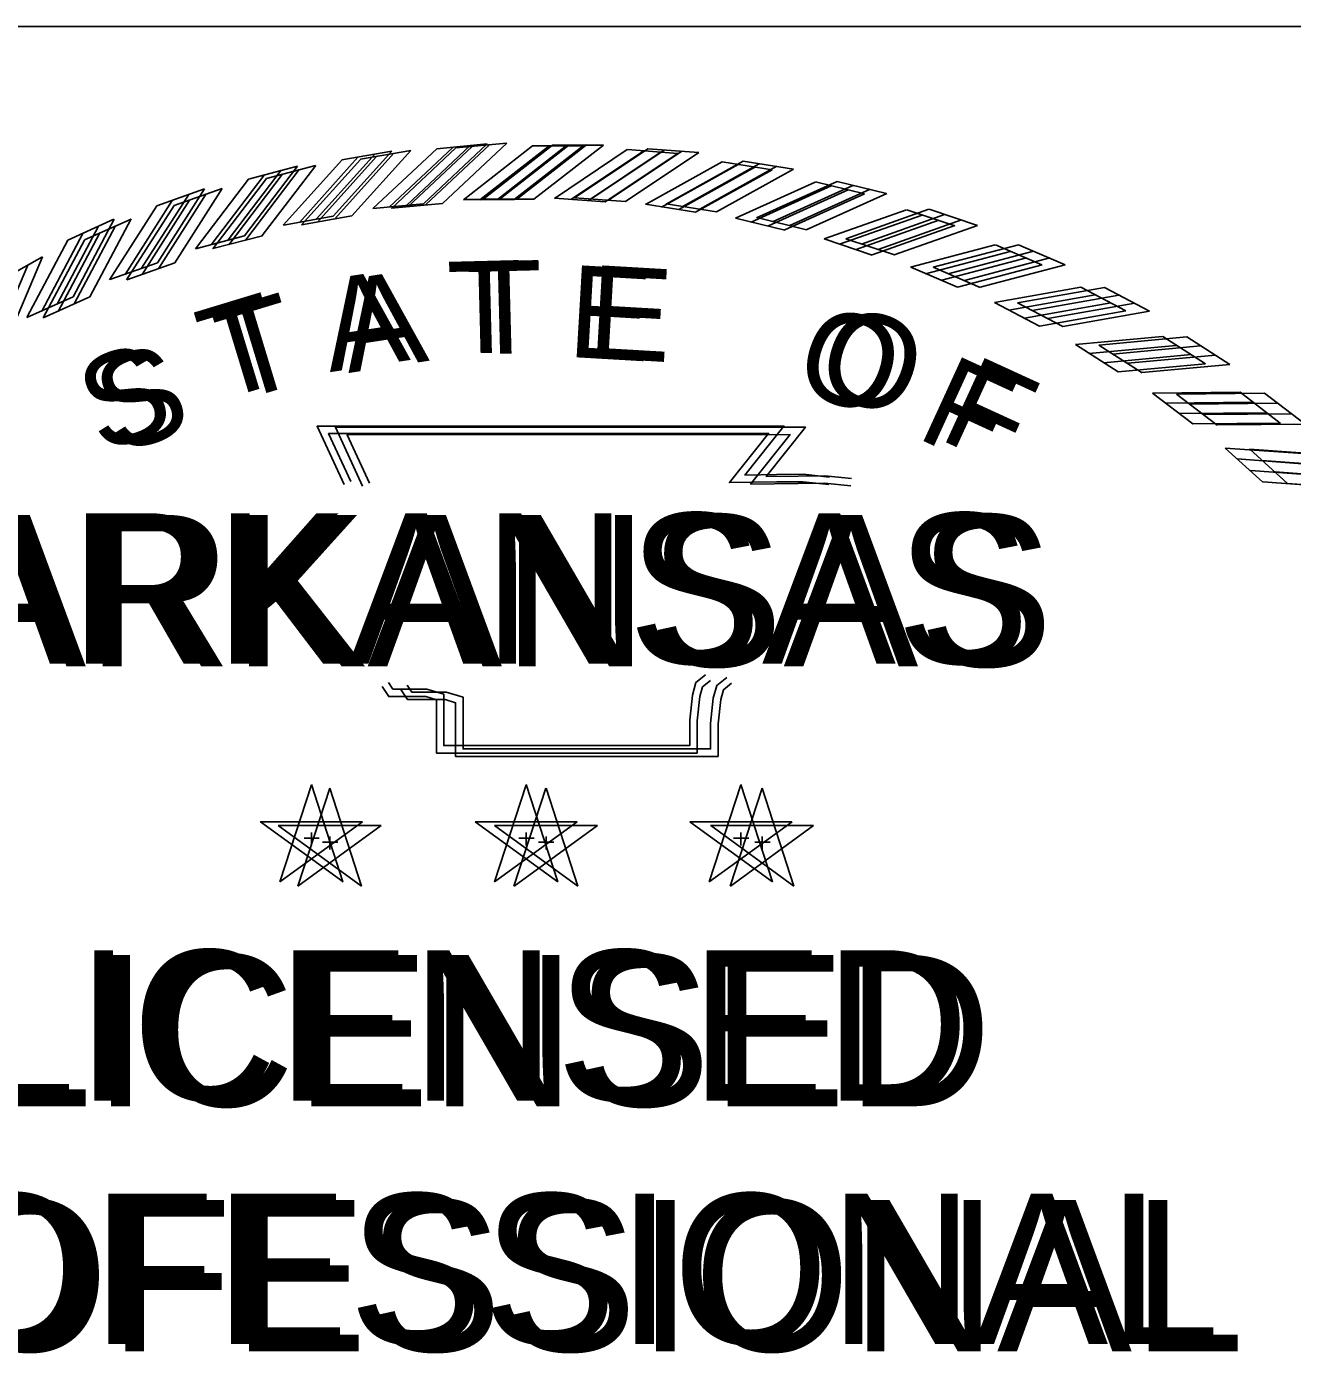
# Model space of a CAD drawing. Extents: x 0 to 1228740, y 0 to 152440.
# Drawn here: x 31.502 to 32.853, y 18.727 to 20.143 of the extents above; entities that cross this region are included whole.
import ezdxf

# ---------------------------------------------------------------- set-up
doc = ezdxf.new("R2010")
doc.units = 0
for name, color, linetype in [('R_Border', 7, 'Continuous'), ('STAMP_Byron', 7, 'Continuous'), ('STAMP_PP', 7, 'Continuous')]:
    doc.layers.add(name, color=color, linetype=linetype)

msp = doc.modelspace()

# ---------------------------------------------------------------- linework, layer by layer
at = {"layer": 'R_Border'}
msp.add_line((29.1131, 20.1432), (33.4231, 20.1432), dxfattribs=at)
at = {"layer": 'STAMP_Byron'}
for p, q in [((31.9398, 20.0128), (31.9936, 20.0178)), ((31.9398, 20.0128), (31.9936, 20.0178)), ((32.0421, 20.0159), (32.0961, 20.0159)), ((32.0421, 20.0159), (32.0961, 20.0159)), ((32.1433, 20.0118), (32.1972, 20.0078)), ((32.1433, 20.0118), (32.1972, 20.0078)), ((31.8386, 20.0008), (31.8918, 20.0101)), ((31.8386, 20.0008), (31.8918, 20.0101)), ((32.2443, 19.9987), (32.2977, 19.9903)), ((32.2443, 19.9987), (32.2977, 19.9903)), ((31.7388, 19.9804), (31.7911, 19.9941)), ((31.7388, 19.9804), (31.7911, 19.9941)), ((31.641, 19.9518), (31.692, 19.9698)), ((31.641, 19.9518), (31.692, 19.9698)), ((32.3439, 19.9773), (32.3964, 19.9645)), ((32.3439, 19.9773), (32.3964, 19.9645)), ((31.9684, 19.9584), (32.0225, 19.9584)), ((31.9684, 19.9584), (32.0225, 19.9584)), ((32.0656, 19.9599), (32.1196, 19.9559)), ((32.0656, 19.9599), (32.1196, 19.9559)), ((31.776, 19.9313), (31.8293, 19.9407)), ((31.776, 19.9313), (31.8293, 19.9407)), ((31.8716, 19.9488), (31.9255, 19.9538)), ((31.8716, 19.9488), (31.9255, 19.9538)), ((32.1626, 19.9534), (32.2161, 19.9449)), ((32.1626, 19.9534), (32.2161, 19.9449)), ((32.4414, 19.9477), (32.4927, 19.9306)), ((32.4414, 19.9477), (32.4927, 19.9306)), ((31.546, 19.9152), (31.5952, 19.9374)), ((31.546, 19.9152), (31.5952, 19.9374)), ((32.2587, 19.9388), (32.3113, 19.926)), ((32.2587, 19.9388), (32.3113, 19.926)), ((31.6821, 19.906), (31.7345, 19.9198)), ((31.6821, 19.906), (31.7345, 19.9198)), ((32.3533, 19.9165), (32.4047, 19.8993)), ((32.3533, 19.9165), (32.4047, 19.8993)), ((32.5361, 19.9102), (32.5858, 19.8889)), ((32.5361, 19.9102), (32.5858, 19.8889)), ((31.5907, 19.873), (31.6417, 19.8911)), ((31.5907, 19.873), (31.6417, 19.8911)), ((32.4457, 19.8863), (32.4955, 19.865)), ((32.4457, 19.8863), (32.4955, 19.865)), ((32.6274, 19.865), (32.6752, 19.8397)), ((32.6274, 19.865), (32.6752, 19.8397)), ((31.5023, 19.8326), (31.5517, 19.8548)), ((31.5023, 19.8326), (31.5517, 19.8548)), ((32.5353, 19.8487), (32.5832, 19.8233)), ((32.5353, 19.8487), (32.5832, 19.8233)), ((32.6215, 19.8037), (32.6672, 19.7745)), ((32.6215, 19.8037), (32.6672, 19.7745)), ((32.7147, 19.8124), (32.7602, 19.7833)), ((32.7147, 19.8124), (32.7602, 19.7833)), ((32.7037, 19.7518), (32.7468, 19.719)), ((32.7037, 19.7518), (32.7468, 19.719)), ((32.7973, 19.7528), (32.8402, 19.72)), ((32.7973, 19.7528), (32.8402, 19.72)), ((32.7814, 19.6933), (32.8216, 19.657)), ((32.7814, 19.6933), (32.8216, 19.657)), ((31.806, 19.334), (31.7721, 19.2303)), ((31.806, 19.334), (31.7721, 19.2303)), ((31.8396, 19.2304), (31.806, 19.3341)), ((31.8396, 19.2304), (31.806, 19.3341)), ((32.0352, 19.334), (32.0014, 19.2303)), ((32.0352, 19.334), (32.0014, 19.2303)), ((32.0689, 19.2304), (32.0352, 19.3341)), ((32.0689, 19.2304), (32.0352, 19.3341)), ((32.2644, 19.334), (32.2306, 19.2303)), ((32.2644, 19.334), (32.2306, 19.2303)), ((32.2981, 19.2304), (32.2645, 19.3341)), ((32.2981, 19.2304), (32.2645, 19.3341)), ((31.8605, 19.2944), (31.7514, 19.2945)), ((31.8605, 19.2944), (31.7514, 19.2945)), ((31.7515, 19.2944), (31.8397, 19.2302)), ((31.7515, 19.2944), (31.8397, 19.2302)), ((31.7723, 19.2304), (31.8606, 19.2944)), ((31.7723, 19.2304), (31.8606, 19.2944)), ((32.0897, 19.2944), (31.9806, 19.2945)), ((32.0897, 19.2944), (31.9806, 19.2945)), ((31.9807, 19.2944), (32.0689, 19.2302)), ((31.9807, 19.2944), (32.0689, 19.2302)), ((32.0015, 19.2304), (32.0898, 19.2944)), ((32.0015, 19.2304), (32.0898, 19.2944)), ((32.3189, 19.2944), (32.2098, 19.2945)), ((32.3189, 19.2944), (32.2098, 19.2945)), ((32.2099, 19.2944), (32.2981, 19.2302)), ((32.2099, 19.2944), (32.2981, 19.2302)), ((32.2307, 19.2304), (32.319, 19.2944)), ((32.2307, 19.2304), (32.319, 19.2944)), ((31.7982, 19.277), (31.8144, 19.277)), ((31.7982, 19.277), (31.8144, 19.277)), ((31.8061, 19.2828), (31.8061, 19.2691)), ((31.8061, 19.2828), (31.8061, 19.2691)), ((32.0274, 19.277), (32.0436, 19.277)), ((32.0274, 19.277), (32.0436, 19.277)), ((32.0353, 19.2828), (32.0353, 19.2691)), ((32.0353, 19.2828), (32.0353, 19.2691)), ((32.2566, 19.277), (32.2728, 19.277)), ((32.2566, 19.277), (32.2728, 19.277)), ((32.2645, 19.2828), (32.2645, 19.2691)), ((32.2645, 19.2828), (32.2645, 19.2691))]:
    msp.add_line(p, q, dxfattribs=at)
for points in [[(31.8715, 19.9488), (31.9397, 20.0128)], [(31.8715, 19.9488), (31.9397, 20.0128)], [(31.8889, 19.9502), (31.957, 20.0142)], [(31.8889, 19.9502), (31.957, 20.0142)], [(31.9075, 19.9523), (31.9757, 20.0164)], [(31.9075, 19.9523), (31.9757, 20.0164)], [(31.9255, 19.9538), (31.9936, 20.0178)], [(31.9255, 19.9538), (31.9936, 20.0178)], [(31.9683, 19.9583), (32.042, 20.0158)], [(31.9683, 19.9583), (32.042, 20.0158)], [(31.9857, 19.9581), (32.0594, 20.0156)], [(31.9857, 19.9581), (32.0594, 20.0156)], [(32.0045, 19.9586), (32.0782, 20.0161)], [(32.0045, 19.9586), (32.0782, 20.0161)], [(32.0225, 19.9584), (32.0962, 20.0159)], [(32.0225, 19.9584), (32.0962, 20.0159)], [(32.0655, 19.9598), (32.1432, 20.0118)], [(32.0655, 19.9598), (32.1432, 20.0118)], [(31.7759, 19.9313), (31.8386, 20.0007)], [(31.7759, 19.9313), (31.8386, 20.0007)], [(31.7931, 19.9341), (31.8557, 20.0036)], [(31.7931, 19.9341), (31.8557, 20.0036)], [(31.8115, 19.9378), (31.8741, 20.0072)], [(31.8115, 19.9378), (31.8741, 20.0072)], [(31.8293, 19.9408), (31.8919, 20.0102)], [(31.8293, 19.9408), (31.8919, 20.0102)], [(32.0828, 19.9584), (32.1606, 20.0103)], [(32.0828, 19.9584), (32.1606, 20.0103)], [(32.1016, 19.9574), (32.1793, 20.0094)], [(32.1016, 19.9574), (32.1793, 20.0094)], [(32.1195, 19.9559), (32.1973, 20.0079)], [(32.1195, 19.9559), (32.1973, 20.0079)], [(32.1625, 19.9533), (32.2443, 19.9986)], [(32.1625, 19.9533), (32.2443, 19.9986)], [(31.6989, 19.9102), (31.7556, 19.9846)], [(31.6989, 19.9102), (31.7556, 19.9846)], [(31.717, 19.9154), (31.7737, 19.9897)], [(31.717, 19.9154), (31.7737, 19.9897)], [(31.7344, 19.9198), (31.7911, 19.9942)], [(31.7344, 19.9198), (31.7911, 19.9942)], [(32.1796, 19.9504), (32.2614, 19.9958)], [(32.1796, 19.9504), (32.2614, 19.9958)], [(32.1982, 19.9479), (32.28, 19.9933)], [(32.1982, 19.9479), (32.28, 19.9933)], [(32.216, 19.945), (32.2978, 19.9903)], [(32.216, 19.945), (32.2978, 19.9903)], [(31.6417, 19.8911), (31.692, 19.9699)], [(31.6417, 19.8911), (31.692, 19.9699)], [(31.6821, 19.9059), (31.7388, 19.9803)], [(31.6821, 19.9059), (31.7388, 19.9803)], [(32.2586, 19.9388), (32.3438, 19.9772)], [(32.2586, 19.9388), (32.3438, 19.9772)], [(32.2755, 19.9345), (32.3607, 19.973)], [(32.2755, 19.9345), (32.3607, 19.973)], [(32.2938, 19.9305), (32.379, 19.9689)], [(32.2938, 19.9305), (32.379, 19.9689)], [(31.6071, 19.8786), (31.6574, 19.9574)], [(31.6071, 19.8786), (31.6574, 19.9574)], [(31.6246, 19.8852), (31.675, 19.964)], [(31.6246, 19.8852), (31.675, 19.964)], [(32.3113, 19.9261), (32.3965, 19.9645)], [(32.3113, 19.9261), (32.3965, 19.9645)], [(31.5906, 19.8729), (31.641, 19.9517)], [(31.5906, 19.8729), (31.641, 19.9517)], [(32.3532, 19.9164), (32.4413, 19.9477)], [(32.3532, 19.9164), (32.4413, 19.9477)], [(32.3697, 19.9108), (32.4578, 19.942)], [(32.3697, 19.9108), (32.4578, 19.942)], [(31.5351, 19.8476), (31.5788, 19.9302)], [(31.5351, 19.8476), (31.5788, 19.9302)], [(31.5516, 19.8548), (31.5953, 19.9375)], [(31.5516, 19.8548), (31.5953, 19.9375)], [(32.3876, 19.9052), (32.4757, 19.9365)], [(32.3876, 19.9052), (32.4757, 19.9365)], [(32.4046, 19.8994), (32.4927, 19.9307)], [(32.4046, 19.8994), (32.4927, 19.9307)], [(31.5022, 19.8325), (31.5459, 19.9152)], [(31.5022, 19.8325), (31.5459, 19.9152)], [(31.5182, 19.8395), (31.5618, 19.9222)], [(31.5182, 19.8395), (31.5618, 19.9222)], [(32.4456, 19.8863), (32.536, 19.9102)], [(32.4456, 19.8863), (32.536, 19.9102)], [(32.4616, 19.8793), (32.552, 19.9032)], [(32.4616, 19.8793), (32.552, 19.9032)], [(32.479, 19.8723), (32.5694, 19.8962)], [(32.479, 19.8723), (32.5694, 19.8962)], [(32.4955, 19.8651), (32.5859, 19.889)], [(32.4955, 19.8651), (32.5859, 19.889)], [(32.5352, 19.8487), (32.6273, 19.865)], [(32.5352, 19.8487), (32.6273, 19.865)], [(32.5505, 19.8404), (32.6426, 19.8567)], [(32.5505, 19.8404), (32.6426, 19.8567)], [(32.5673, 19.832), (32.6594, 19.8483)], [(32.5673, 19.832), (32.6594, 19.8483)], [(32.5832, 19.8234), (32.6752, 19.8397)], [(32.5832, 19.8234), (32.6752, 19.8397)], [(32.6215, 19.8037), (32.7146, 19.8124)], [(32.6215, 19.8037), (32.7146, 19.8124)], [(32.636, 19.7942), (32.7291, 19.8029)], [(32.636, 19.7942), (32.7291, 19.8029)], [(32.652, 19.7844), (32.7452, 19.7931)], [(32.652, 19.7844), (32.7452, 19.7931)], [(32.6671, 19.7746), (32.7602, 19.7833)], [(32.6671, 19.7746), (32.7602, 19.7833)], [(32.7037, 19.7518), (32.7972, 19.7528)], [(32.7037, 19.7518), (32.7972, 19.7528)], [(32.7174, 19.7412), (32.8109, 19.7421)], [(32.7174, 19.7412), (32.8109, 19.7421)], [(32.7326, 19.7301), (32.8261, 19.731)], [(32.7326, 19.7301), (32.8261, 19.731)], [(31.8408, 19.6542), (31.812, 19.7166), (32.3104, 19.7168), (32.2687, 19.6645), (32.3026, 19.665), (32.3309, 19.6653), (32.3591, 19.6623)], [(31.8408, 19.6542), (31.812, 19.7166), (32.3104, 19.7168), (32.2687, 19.6645), (32.3026, 19.665), (32.3309, 19.6653), (32.3591, 19.6623)], [(32.7468, 19.719), (32.8403, 19.72)], [(32.7468, 19.719), (32.8403, 19.72)], [(31.8479, 19.6575), (31.8243, 19.7087), (32.294, 19.7089), (32.2522, 19.6564), (32.3027, 19.6571), (32.3305, 19.6574), (32.3583, 19.6544)], [(31.8479, 19.6575), (31.8243, 19.7087), (32.294, 19.7089), (32.2522, 19.6564), (32.3027, 19.6571), (32.3305, 19.6574), (32.3583, 19.6544)], [(32.7813, 19.6933), (32.8746, 19.6866)], [(32.7813, 19.6933), (32.8746, 19.6866)], [(32.7941, 19.6816), (32.8874, 19.6748)], [(32.7941, 19.6816), (32.8874, 19.6748)], [(32.8083, 19.6693), (32.9016, 19.6625)], [(32.8083, 19.6693), (32.9016, 19.6625)], [(32.8215, 19.6571), (32.9148, 19.6503)], [(32.8215, 19.6571), (32.9148, 19.6503)], [(32.2318, 19.4453), (32.2233, 19.4384), (32.2205, 19.4281), (32.2177, 19.4022), (32.2177, 19.3678), (31.9395, 19.3678), (31.9395, 19.4143), (31.9395, 19.4246), (31.9282, 19.4281), (31.8886, 19.4281), (31.8816, 19.4388)], [(32.2318, 19.4453), (32.2233, 19.4384), (32.2205, 19.4281), (32.2177, 19.4022), (32.2177, 19.3678), (31.9395, 19.3678), (31.9395, 19.4143), (31.9395, 19.4246), (31.9282, 19.4281), (31.8886, 19.4281), (31.8816, 19.4388)], [(32.2268, 19.4514), (32.2164, 19.4429), (32.2127, 19.4295), (32.2098, 19.4027), (32.2098, 19.3757), (31.9473, 19.3757), (31.9473, 19.4143), (31.9473, 19.4305), (31.9293, 19.436), (31.8929, 19.436), (31.8882, 19.4431)], [(32.2268, 19.4514), (32.2164, 19.4429), (32.2127, 19.4295), (32.2098, 19.4027), (32.2098, 19.3757), (31.9473, 19.3757), (31.9473, 19.4143), (31.9473, 19.4305), (31.9293, 19.436), (31.8929, 19.436), (31.8882, 19.4431)]]:
    msp.add_lwpolyline(points, dxfattribs=at)
at = {"layer": 'STAMP_PP'}
for p, q in [((31.9602, 20.0137), (32.0144, 20.0186)), ((32.0633, 20.0167), (32.1177, 20.0167)), ((32.1652, 20.0126), (32.2194, 20.0086)), ((31.8584, 20.0015), (31.912, 20.0109)), ((32.2669, 19.9994), (32.3206, 19.9909)), ((31.7579, 19.981), (31.8105, 19.9948)), ((31.6595, 19.9522), (31.7108, 19.9703)), ((32.3671, 19.9778), (32.42, 19.965)), ((31.989, 19.9588), (32.0435, 19.9588)), ((32.0869, 19.9603), (32.1413, 19.9563)), ((31.7953, 19.9316), (31.849, 19.941)), ((31.8916, 19.9492), (31.9459, 19.9542)), ((32.1845, 19.9538), (32.2384, 19.9453)), ((32.4653, 19.9481), (32.5169, 19.9309)), ((31.5637, 19.9154), (31.6134, 19.9377)), ((32.2813, 19.9392), (32.3343, 19.9263)), ((31.7008, 19.9061), (31.7536, 19.9199)), ((32.3766, 19.9166), (32.4283, 19.8994)), ((32.5606, 19.9103), (32.6107, 19.8889)), ((31.4714, 19.8708), (31.519, 19.8972)), ((31.6088, 19.8729), (31.6602, 19.891)), ((32.4696, 19.8863), (32.5198, 19.8648)), ((32.6526, 19.8648), (32.7006, 19.8393)), ((31.5198, 19.8321), (31.5695, 19.8545)), ((32.5598, 19.8484), (32.608, 19.8229)), ((32.6466, 19.8031), (32.6926, 19.7737)), ((32.7404, 19.8119), (32.7862, 19.7825)), ((32.7294, 19.7509), (32.7727, 19.7178)), ((32.8235, 19.7518), (32.8668, 19.7188)), ((32.8076, 19.692), (32.848, 19.6554)), ((31.8255, 19.3302), (31.7915, 19.2258)), ((31.8594, 19.2258), (31.8256, 19.3303)), ((32.0563, 19.3302), (32.0222, 19.2258)), ((32.0902, 19.2258), (32.0564, 19.3303)), ((32.2871, 19.3302), (32.253, 19.2258)), ((32.321, 19.2258), (32.2871, 19.3303)), ((31.8804, 19.2904), (31.7705, 19.2905)), ((31.7706, 19.2904), (31.8594, 19.2257)), ((31.7916, 19.2258), (31.8805, 19.2903)), ((32.1112, 19.2904), (32.0013, 19.2905)), ((32.0014, 19.2904), (32.0902, 19.2257)), ((32.0224, 19.2258), (32.1113, 19.2903)), ((32.3419, 19.2904), (32.2321, 19.2905)), ((32.2322, 19.2904), (32.321, 19.2257)), ((32.2532, 19.2258), (32.3421, 19.2903)), ((31.8256, 19.2787), (31.8256, 19.2649)), ((32.0564, 19.2787), (32.0564, 19.2649)), ((32.2872, 19.2787), (32.2872, 19.2649)), ((31.8177, 19.2728), (31.834, 19.2728)), ((32.0485, 19.2728), (32.0648, 19.2728)), ((32.2793, 19.2728), (32.2956, 19.2728))]:
    msp.add_line(p, q, dxfattribs=at)
for points in [[(31.8916, 19.9491), (31.9602, 20.0136)], [(31.909, 19.9506), (31.9776, 20.015)], [(31.9278, 19.9527), (31.9964, 20.0172)], [(31.9458, 19.9542), (32.0145, 20.0187)], [(31.9889, 19.9587), (32.0632, 20.0166)], [(32.0065, 19.9586), (32.0807, 20.0165)], [(32.0254, 19.959), (32.0996, 20.0169)], [(32.0435, 19.9588), (32.1177, 20.0167)], [(32.0868, 19.9603), (32.1651, 20.0126)], [(31.7953, 19.9315), (31.8583, 20.0014)], [(31.8126, 19.9344), (31.8756, 20.0043)], [(31.8311, 19.9381), (31.8941, 20.008)], [(31.849, 19.9411), (31.912, 20.011)], [(32.1043, 19.9588), (32.1825, 20.0111)], [(32.1231, 19.9579), (32.2014, 20.0101)], [(32.1412, 19.9564), (32.2195, 20.0087)], [(32.1845, 19.9537), (32.2668, 19.9994)], [(31.7178, 19.9103), (31.7748, 19.9852)], [(31.7359, 19.9155), (31.793, 19.9904)], [(31.7535, 19.92), (31.8106, 19.9948)], [(32.2017, 19.9508), (32.2841, 19.9965)], [(32.2205, 19.9483), (32.3028, 19.994)], [(32.2383, 19.9453), (32.3207, 19.991)], [(31.6601, 19.8911), (31.7108, 19.9704)], [(31.7008, 19.906), (31.7579, 19.9809)], [(32.2812, 19.9391), (32.3671, 19.9778)], [(32.2982, 19.9348), (32.384, 19.9735)], [(32.3167, 19.9308), (32.4025, 19.9695)], [(31.6253, 19.8785), (31.676, 19.9578)], [(31.643, 19.8852), (31.6937, 19.9645)], [(32.3342, 19.9263), (32.4201, 19.965)], [(31.6087, 19.8728), (31.6594, 19.9521)], [(32.3765, 19.9166), (32.4652, 19.9481)], [(32.393, 19.9109), (32.4818, 19.9424)], [(31.5528, 19.8472), (31.5968, 19.9305)], [(31.5694, 19.8545), (31.6134, 19.9378)], [(32.4111, 19.9053), (32.4998, 19.9368)], [(32.4282, 19.8994), (32.517, 19.9309)], [(31.5197, 19.8321), (31.5637, 19.9153)], [(31.5358, 19.8391), (31.5797, 19.9224)], [(32.4695, 19.8863), (32.5606, 19.9103)], [(32.4856, 19.8792), (32.5766, 19.9033)], [(31.4661, 19.802), (31.5031, 19.8886)], [(31.4821, 19.8106), (31.519, 19.8972)], [(32.5031, 19.8722), (32.5941, 19.8962)], [(32.5197, 19.8649), (32.6107, 19.8889)], [(32.5598, 19.8483), (32.6525, 19.8648)], [(32.5752, 19.84), (32.6679, 19.8565)], [(32.5921, 19.8315), (32.6848, 19.848)], [(32.608, 19.8229), (32.7007, 19.8394)], [(32.6466, 19.8031), (32.7403, 19.8119)], [(32.6612, 19.7935), (32.755, 19.8023)], [(32.6774, 19.7837), (32.7711, 19.7924)], [(32.6925, 19.7738), (32.7863, 19.7825)], [(32.7293, 19.7509), (32.8235, 19.7518)], [(32.7431, 19.7401), (32.8373, 19.7411)], [(32.7584, 19.729), (32.8526, 19.7299)], [(31.8606, 19.6525), (31.8316, 19.7154), (32.3333, 19.7156), (32.2914, 19.663), (32.3255, 19.6634), (32.354, 19.6638), (32.3824, 19.6607)], [(32.7727, 19.7179), (32.8669, 19.7188)], [(31.8678, 19.6559), (31.844, 19.7074), (32.3169, 19.7077), (32.2748, 19.6548), (32.3256, 19.6555), (32.3536, 19.6558), (32.3816, 19.6528)], [(32.8075, 19.692), (32.9014, 19.6852)], [(32.8204, 19.6801), (32.9143, 19.6733)], [(32.8347, 19.6678), (32.9286, 19.6609)], [(32.848, 19.6555), (32.9419, 19.6487)], [(32.2493, 19.4484), (32.2387, 19.4399), (32.235, 19.4264), (32.2321, 19.3993), (32.2321, 19.3721), (31.9679, 19.3721), (31.9679, 19.411), (31.9679, 19.4273), (31.9497, 19.4328), (31.913, 19.4328), (31.9083, 19.4401)], [(32.2543, 19.4423), (32.2457, 19.4353), (32.2429, 19.4249), (32.24, 19.3989), (32.24, 19.3642), (31.9599, 19.3642), (31.9599, 19.411), (31.9599, 19.4214), (31.9486, 19.4249), (31.9087, 19.4249), (31.9016, 19.4357)]]:
    msp.add_lwpolyline(points, dxfattribs=at)

# ---------------------------------------------------------------- texts
at = {"layer": 'STAMP_Byron'}
for s, rotation, p in [('T', 1.4789, (31.9525, 19.7937)), ('T', 1.4789, (31.9525, 19.7937)), ('E', 356.672, (32.0783, 19.7907)), ('E', 356.672, (32.0783, 19.7907)), ('A', 8.6788, (31.8256, 19.7742)), ('A', 8.6788, (31.8256, 19.7742)), ('T', 16.9015, (31.7062, 19.743)), ('T', 16.9015, (31.7062, 19.743)), ('O', 341.2218, (32.3171, 19.757)), ('O', 341.2218, (32.3171, 19.757)), ('S', 19.7726, (31.5812, 19.6869)), ('S', 19.7726, (31.5812, 19.6869)), ('F', 335.3628, (32.4496, 19.7052)), ('F', 335.3628, (32.4496, 19.7052))]:
    msp.add_text(s, height=0.0983, rotation=rotation, dxfattribs=at).set_placement(p)
for s, height, p in [('ARKANSAS', 0.16046, (31.4045, 19.4632)), ('ARKANSAS', 0.16046, (31.4045, 19.4632)), ('LICENSED', 0.16046, (31.4351, 18.9969)), ('LICENSED', 0.16046, (31.4351, 18.9969)), ('PROFESSIONAL', 0.160455, (31.1066, 18.7371)), ('PROFESSIONAL', 0.160455, (31.1066, 18.7371))]:
    msp.add_text(s, height=height, dxfattribs=at).set_placement(p)
at = {"layer": 'STAMP_PP'}
for s, rotation, p in [('T', 1.4789, (31.9731, 19.793)), ('E', 356.672, (32.0998, 19.79)), ('A', 8.6788, (31.8453, 19.7733)), ('T', 16.9015, (31.7251, 19.742)), ('O', 341.2218, (32.3401, 19.7561)), ('S', 19.7726, (31.5992, 19.6855)), ('F', 335.3628, (32.4735, 19.7039))]:
    msp.add_text(s, height=0.099, rotation=rotation, dxfattribs=at).set_placement(p)
for s, height, p in [('ARKANSAS', 0.16155, (31.4214, 19.4603)), ('LICENSED', 0.16155, (31.4521, 18.9908)), ('PROFESSIONAL', 0.161547, (31.1214, 18.7292))]:
    msp.add_text(s, height=height, dxfattribs=at).set_placement(p)

doc.saveas('drawing.dxf')
